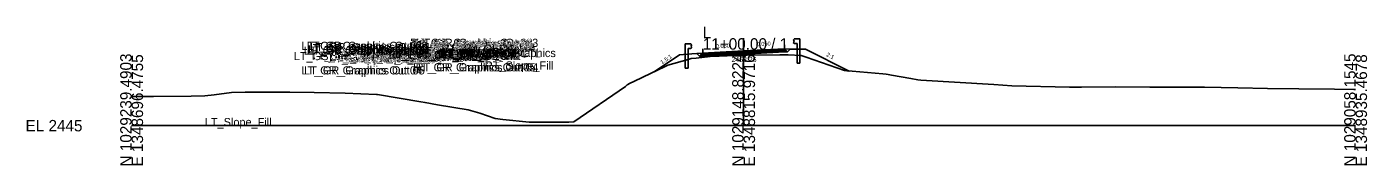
# Model space of a CAD drawing. Extents: x -26 to 1453, y -10 to 4527.
# Drawn here: x -25.7 to 302.8, y 990.3 to 1024.2 of the extents above; entities that cross this region are included whole.
import ezdxf

# ---------------------------------------------------------------- set-up
doc = ezdxf.new("R2010")
doc.units = 0
for name, color, linetype in [('Default', 7, 'Continuous'), ('Exist Cross Section Cell', 7, 'Continuous'), ('Exist XS Center Line Elevation Label', 7, 'Continuous'), ('Exist XS Ground Line', 7, 'Continuous'), ('Prop CMT Guardrail Graphics', 7, 'Continuous'), ('Prop CMT Pvmt Course 1', 7, 'Continuous'), ('Prop CMT Pvmt Course 2', 7, 'Continuous'), ('Prop CMT Pvmt Course 3', 7, 'Continuous'), ('Prop CMT Pvmt Surface', 7, 'Continuous'), ('Prop CMT Pvmt Surface Overlay', 7, 'Continuous'), ('Prop CMT Pvmt Surface Shoulder', 7, 'Continuous'), ('Prop CMT Shld Paved Course 1', 7, 'Continuous'), ('Prop CMT Shld Paved Course 2', 7, 'Continuous'), ('Prop CMT Shld Paved Course 3', 7, 'Continuous'), ('Prop CMT Slope Grass', 7, 'Continuous'), ('Prop CMT Subgrade Earthwork', 7, 'Continuous'), ('Prop XS Earthwork Shape', 7, 'Continuous'), ('Prop XS EOT Tick Mark', 7, 'Continuous'), ('Prop XS SE Text', 7, 'Continuous'), ('Prop XS Side Slope Text', 7, 'Continuous')]:
    doc.layers.add(name, color=color, linetype=linetype)

msp = doc.modelspace()

# ---------------------------------------------------------------- linework, layer by layer
at = {"layer": 'Exist Cross Section Cell'}
for p, q in [((150, 1000), (150, 1021.43)), ((0, 1000), (150, 1000)), ((150, 1000), (300, 1000))]:
    msp.add_line(p, q, dxfattribs=at)
at = {"layer": 'Exist XS Ground Line'}
msp.add_lwpolyline([(0, 1007.14), (5.34, 1007.11), (14.6, 1007.27), (17.95, 1007.31), (20.21, 1007.59), (24.44, 1008.15), (27.81, 1008.21), (38.81, 1008.22), (44.71, 1008.11), (52.35, 1008), (59.98, 1007.67), (60.25, 1007.65), (70.87, 1005.86), (71.92, 1005.66), (75.01, 1005.12), (82.48, 1003.88), (85.38, 1003.08), (89.13, 1001.74), (90.96, 1001.53), (97.45, 1000.89), (107.13, 1000.88), (108.42, 1000.96), (121.01, 1009.57), (121.49, 1009.98), (122.23, 1010.39), (123.13, 1010.82), (131.39, 1014.79), (136.38, 1016.25), (137.15, 1016.46), (138.39, 1016.58), (141.83, 1016.95), (144, 1017.02), (150, 1017.25), (150.87, 1017.28), (158.88, 1017.35), (160.26, 1017.36), (160.89, 1017.33), (164.1, 1017.16), (165.33, 1016.77), (174.73, 1013.49), (184.11, 1012.67), (184.96, 1012.6), (185.44, 1012.53), (186.21, 1012.39), (191.01, 1011.53), (192.73, 1011.2), (193.46, 1011.18), (211.32, 1010.09), (215.77, 1009.78), (229.87, 1009.47), (232.82, 1009.42), (241.11, 1009.5), (249.54, 1009.47), (256.92, 1009.46), (261.07, 1009.45), (262.98, 1009.44), (271.15, 1009.26), (278.39, 1009.15), (286.12, 1009.03), (294.79, 1008.98), (300, 1008.89)], dxfattribs=at)
at = {"layer": 'Prop CMT Guardrail Graphics'}
for points in [[(135.71, 1014.09), (135.71, 1020.09)], [(135.71, 1020.09), (137.04, 1020.09), (137.31, 1019.8)], [(137.31, 1019.22), (137.04, 1018.93), (136.37, 1018.93)], [(136.37, 1018.93), (136.37, 1014.09)], [(137.31, 1019.8), (137.04, 1019.51)], [(137.04, 1019.51), (137.31, 1019.22)], [(163.78, 1021.29), (162.44, 1021.29), (162.17, 1020.99)], [(162.17, 1020.99), (162.44, 1020.7)], [(162.44, 1020.7), (162.17, 1020.41)], [(162.17, 1020.41), (162.44, 1020.12), (163.11, 1020.12)], [(163.11, 1020.12), (163.11, 1015.29)], [(163.78, 1015.29), (163.78, 1021.29)], [(163.11, 1015.29), (163.78, 1015.29)], [(136.37, 1014.09), (135.71, 1014.09)]]:
    msp.add_lwpolyline(points, dxfattribs=at)
at = {"layer": 'Prop CMT Pvmt Course 1'}
for points in [[(150, 1018.31), (160, 1018.81)], [(160, 1018.56), (150, 1018.06)], [(160, 1018.81), (160, 1018.56)], [(150, 1018.31), (140, 1017.81)], [(140, 1017.56), (150, 1018.06)], [(140, 1017.81), (140, 1017.56)], [(150, 1018.18), (150, 1018.31)], [(150, 1018.18), (150, 1018.31)], [(150, 1018.06), (150, 1018.18), (150, 1018.18)], [(150, 1018.06), (150, 1018.18), (150, 1018.18)]]:
    msp.add_lwpolyline(points, dxfattribs=at)
at = {"layer": 'Prop CMT Pvmt Course 2'}
for points in [[(150, 1018.06), (160, 1018.56)], [(160, 1018.56), (160, 1018.31)], [(150, 1018.06), (140, 1017.56)], [(140, 1017.31), (150, 1017.81)], [(140, 1017.56), (140, 1017.31)], [(160, 1018.31), (150, 1017.81)], [(150, 1017.81), (150, 1018.06)], [(150, 1017.81), (150, 1018.06)]]:
    msp.add_lwpolyline(points, dxfattribs=at)
at = {"layer": 'Prop CMT Pvmt Course 3'}
for points in [[(150, 1017.81), (140, 1017.31)], [(140, 1017.06), (150, 1017.56)], [(140, 1017.31), (140, 1017.06)], [(150, 1017.81), (160, 1018.31)], [(160, 1018.06), (150, 1017.56)], [(150, 1017.56), (150, 1017.81)], [(150, 1017.56), (150, 1017.81)], [(160, 1018.31), (160, 1018.06)]]:
    msp.add_lwpolyline(points, dxfattribs=at)
at = {"layer": 'Prop CMT Pvmt Surface'}
for points in [[(150, 1018.31), (160, 1018.81)], [(150, 1018.31), (140, 1017.81)]]:
    msp.add_lwpolyline(points, dxfattribs=at)
at = {"layer": 'Prop CMT Pvmt Surface Overlay'}
for points in [[(150, 1018.31), (160, 1018.81)], [(150, 1018.31), (140, 1017.81)]]:
    msp.add_lwpolyline(points, dxfattribs=at)
at = {"layer": 'Prop CMT Pvmt Surface Shoulder'}
for points in [[(160, 1018.81), (160, 1018.81)], [(140, 1017.81), (140, 1017.81)]]:
    msp.add_lwpolyline(points, dxfattribs=at)
at = {"layer": 'Prop CMT Shld Paved Course 1'}
for points in [[(160, 1018.81), (160, 1018.81), (160.24, 1018.57)], [(160, 1018.56), (160, 1018.81)], [(160.24, 1018.57), (160, 1018.56)], [(140, 1017.81), (140, 1017.81), (139.74, 1017.55)], [(139.74, 1017.55), (140, 1017.56)], [(140, 1017.56), (140, 1017.81)]]:
    msp.add_lwpolyline(points, dxfattribs=at)
at = {"layer": 'Prop CMT Shld Paved Course 2'}
for points in [[(160, 1018.56), (160.24, 1018.57), (160.48, 1018.33)], [(160, 1018.31), (160, 1018.56)], [(140, 1017.56), (139.74, 1017.55), (139.47, 1017.28)], [(139.47, 1017.28), (140, 1017.31)], [(140, 1017.31), (140, 1017.56)], [(160.48, 1018.33), (160, 1018.31)]]:
    msp.add_lwpolyline(points, dxfattribs=at)
at = {"layer": 'Prop CMT Shld Paved Course 3'}
for points in [[(139.47, 1017.28), (139.21, 1017.02)], [(139.21, 1017.02), (140, 1017.06)], [(140, 1017.31), (139.47, 1017.28)], [(139.47, 1017.28), (139.47, 1017.28)], [(140, 1017.06), (140, 1017.31)], [(160, 1018.31), (160.48, 1018.33)], [(160, 1018.06), (160, 1018.31)], [(160.72, 1018.09), (160, 1018.06)], [(160.48, 1018.33), (160.48, 1018.33)], [(160.48, 1018.33), (160.72, 1018.09)]]:
    msp.add_lwpolyline(points, dxfattribs=at)
at = {"layer": 'Prop CMT Slope Grass'}
for points in [[(160, 1018.81), (162.17, 1018.79)], [(162.17, 1018.79), (165.17, 1018.76)], [(165.17, 1018.76), (175.91, 1013.39)], [(134.31, 1017.35), (128.1, 1013.21)], [(137.31, 1017.59), (134.31, 1017.35)], [(140, 1017.81), (137.31, 1017.59)]]:
    msp.add_lwpolyline(points, dxfattribs=at)
at = {"layer": 'Prop CMT Subgrade Earthwork'}
for points in [[(160.72, 1018.09), (161.42, 1018.79)], [(139.21, 1017.02), (138.54, 1017.69)], [(140, 1017.06), (139.21, 1017.02)], [(150, 1017.56), (140, 1017.06)], [(150, 1017.56), (160, 1018.06)], [(160, 1018.06), (160.72, 1018.09)]]:
    msp.add_lwpolyline(points, dxfattribs=at)
at = {"layer": 'Prop XS Earthwork Shape'}
msp.add_lwpolyline([(150, 1017.56), (140, 1017.06), (139.21, 1017.02), (138.54, 1017.69), (137.31, 1017.59), (134.31, 1017.35), (128.1, 1013.21), (131.39, 1014.79), (136.38, 1016.25), (137.15, 1016.46), (138.39, 1016.58), (141.83, 1016.95), (144, 1017.02), (150, 1017.25), (150.87, 1017.28), (158.88, 1017.35), (160.26, 1017.36), (160.89, 1017.33), (164.1, 1017.16), (165.33, 1016.77), (174.73, 1013.49), (175.91, 1013.39), (165.17, 1018.76), (162.17, 1018.79), (161.42, 1018.79), (160.72, 1018.09), (160, 1018.06)], close=True, dxfattribs=at)
msp.add_lwpolyline([(150, 1017.56), (140, 1017.06), (139.21, 1017.02), (138.54, 1017.69), (137.31, 1017.59), (134.31, 1017.35), (128.1, 1013.21), (131.39, 1014.79), (136.38, 1016.25), (137.15, 1016.46), (138.39, 1016.58), (141.83, 1016.95), (144, 1017.02), (150, 1017.25), (150.87, 1017.28), (158.88, 1017.35), (160.26, 1017.36), (160.89, 1017.33), (164.1, 1017.16), (165.33, 1016.77), (174.73, 1013.49), (175.91, 1013.39), (165.17, 1018.76), (162.17, 1018.79), (161.42, 1018.79), (160.72, 1018.09), (160, 1018.06)], close=True, dxfattribs=at)
at = {"layer": 'Prop XS EOT Tick Mark'}
for points in [[(140, 1017.81), (140, 1018.81)], [(160, 1018.81), (160, 1019.81)]]:
    msp.add_lwpolyline(points, dxfattribs=at)

# ---------------------------------------------------------------- texts
at = {"layer": 'Default'}
for s, height, p in [('LT_GR_Graphics Out 03', 2, (41.61, 1018.56)), ('LT_GR_Graphics Out 06', 2, (42.22, 1017.4)), ('LT_GR_Graphics Out 02', 2, (42.94, 1018.56)), ('LT_GR_Graphics Out 09', 2, (42.94, 1017.98)), ('LT_GR_Graphics Out 07', 2, (42.94, 1017.4)), ('LT_GR_Graphics Out 08', 2, (43.21, 1017.69)), ('LT_GR_Graphics Out 01', 2, (43.78, 1018.27)), ('LT_TM_OEOT', 2, (55.94, 1017.28)), ('RT_PV1_OEEOP_W', 2, (62.94, 1016.45)), ('LT_PV1_OEEOP_W', 2, (62.98, 1016.45)), ('RT_GS_OS_GR_Face_Graphics', 2, (64.58, 1016.81)), ('RT_Sub_Trench_Out_DLT', 2, (66.93, 1016.84)), ('PV1_PGL_W', 2, (67.58, 1016.45)), ('RT_GR_Graphics Out 08', 2, (68.02, 1018.44)), ('RT_GR_Graphics Out 02', 2, (68.29, 1019.31)), ('RT_GR_Graphics Out 09', 2, (68.29, 1018.73)), ('RT_GR_Graphics Out 07', 2, (68.29, 1018.15)), ('RT_GR_Graphics Out 01', 2, (68.59, 1019.02)), ('RT_GR_Graphics Out 06', 2, (68.91, 1018.15)), ('PV1_PGL', 2, (69.47, 1016.58)), ('RT_GR_Graphics Out 03', 2, (69.63, 1019.31)), ('RT_PS3_Shelf_Out', 2, (71.42, 1016.39)), ('RT_PV2_OEOT', 2, (75.13, 1016.63)), ('RT_PS2_OEOP', 2, (75.43, 1016.64)), ('RT_PV1_OEOT', 2, (75.69, 1016.88)), ('RT_PS1_OEOP', 2, (75.76, 1016.88)), ('RT_TM_OEOT', 2, (75.9, 1017.88)), ('RT_GS_OS_CTL', 2, (79.49, 1016.72)), ('LT_GS_OS_GR_Face_Graphics', 2, (39.77, 1016.06)), ('LT_Sub_Trench_Out_DLT', 2, (44.13, 1016.16)), ('LT_Sub_Trench_Out', 2, (48.43, 1015.51)), ('LT_GS_OS_CTL', 2, (48.68, 1015.82)), ('LT_PS3_Shelf_Out', 2, (50.47, 1015.76)), ('LT_PS3_OEOP', 2, (54.72, 1015.76)), ('LT_PS2_OEOP', 2, (54.98, 1016.02)), ('LT_Sub_OEOT', 2, (55.08, 1015.53)), ('LT_PV2_OEOT', 2, (55.17, 1016.03)), ('LT_PV3_OEOT', 2, (55.17, 1015.78)), ('LT_PV1_OEOT', 2, (55.74, 1016.28)), ('LT_PS1_OEOP', 2, (55.8, 1016.28)), ('RT_Sub_OEEOP', 2, (64.17, 1015.83)), ('LT_Sub_OEEOP', 2, (64.21, 1015.83)), ('RT_PV2_OEEOP', 2, (64.26, 1016.33)), ('RT_PV3_OEEOP', 2, (64.26, 1016.08)), ('LT_PV2_OEEOP', 2, (64.31, 1016.33)), ('LT_PV3_OEEOP', 2, (64.31, 1016.08)), ('RT_GR_Graphics Out 05', 2, (68.96, 1013.31)), ('RT_GR_Graphics Out 04', 2, (69.63, 1013.31)), ('RT_Sub_Trench_Out', 2, (69.89, 1016.15)), ('RT_Sub_OEOT', 2, (75.03, 1016.13)), ('RT_PV3_OEOT', 2, (75.13, 1016.38)), ('RT_PS3_OEOP', 2, (75.68, 1016.39)), ('RT_Slope_Fill', 2, (86.59, 1013.75)), ('LT_GR_Graphics Out 04', 2, (41.61, 1012.56)), ('LT_GR_Graphics Out 05', 2, (42.27, 1012.56)), ('-', 0.0001, (0, 1000)), ('-', 0.0001, (0, 1000)), ('-', 0.0001, (0, 1000)), ('-', 0.0001, (0, 1000)), ('LT_Slope_Fill', 2, (17.95, 999.88))]:
    msp.add_text(s, height=height, dxfattribs=at).set_placement(p)
at = {"layer": 'Exist Cross Section Cell'}
for s, p in [('L', (140, 1021.43)), ('11+00.00 / 1', (140, 1018.63)), ('EL 2445', (-26, 998.6))]:
    msp.add_text(s, height=2.8, dxfattribs=at).set_placement(p)
for s, p in [('N 1029239.4903', (0, 990)), ('E 1348696.4755', (2.8, 990)), ('N 1029148.8224', (150, 990)), ('E 1348815.9716', (152.8, 990)), ('N 1029058.1545', (300, 990)), ('E 1348935.4678', (302.8, 990))]:
    msp.add_text(s, height=2.8, rotation=90, dxfattribs=at).set_placement(p)
at = {"layer": 'Exist XS Center Line Elevation Label'}
msp.add_text('2462.25', height=1.23, dxfattribs=at).set_placement((147.02, 1015.6))
at = {"layer": 'Prop XS SE Text'}
for p in [(143.2, 1018.97), (153.2, 1019.47)]:
    msp.add_text('0.050', height=1, rotation=2.8624, dxfattribs=at).set_placement(p)
at = {"layer": 'Prop XS Side Slope Text'}
for s, rotation, p in [('1.5:1', 33.6901, (130, 1015.02)), ('2:1', 333.4349, (170.17, 1017.1))]:
    msp.add_text(s, height=1, rotation=rotation, dxfattribs=at).set_placement(p)

doc.saveas('drawing.dxf')
